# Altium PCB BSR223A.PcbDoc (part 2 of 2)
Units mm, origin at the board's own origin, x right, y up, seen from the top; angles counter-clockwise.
Board outline 76.2 x 76.2 mm, 4 copper layers (Top Layer, GND Layer 1, GND Layer 2, Bottom Layer), stack 1.554 mm thick; 57 components, 15 nets, 85 pads, 327 vias.
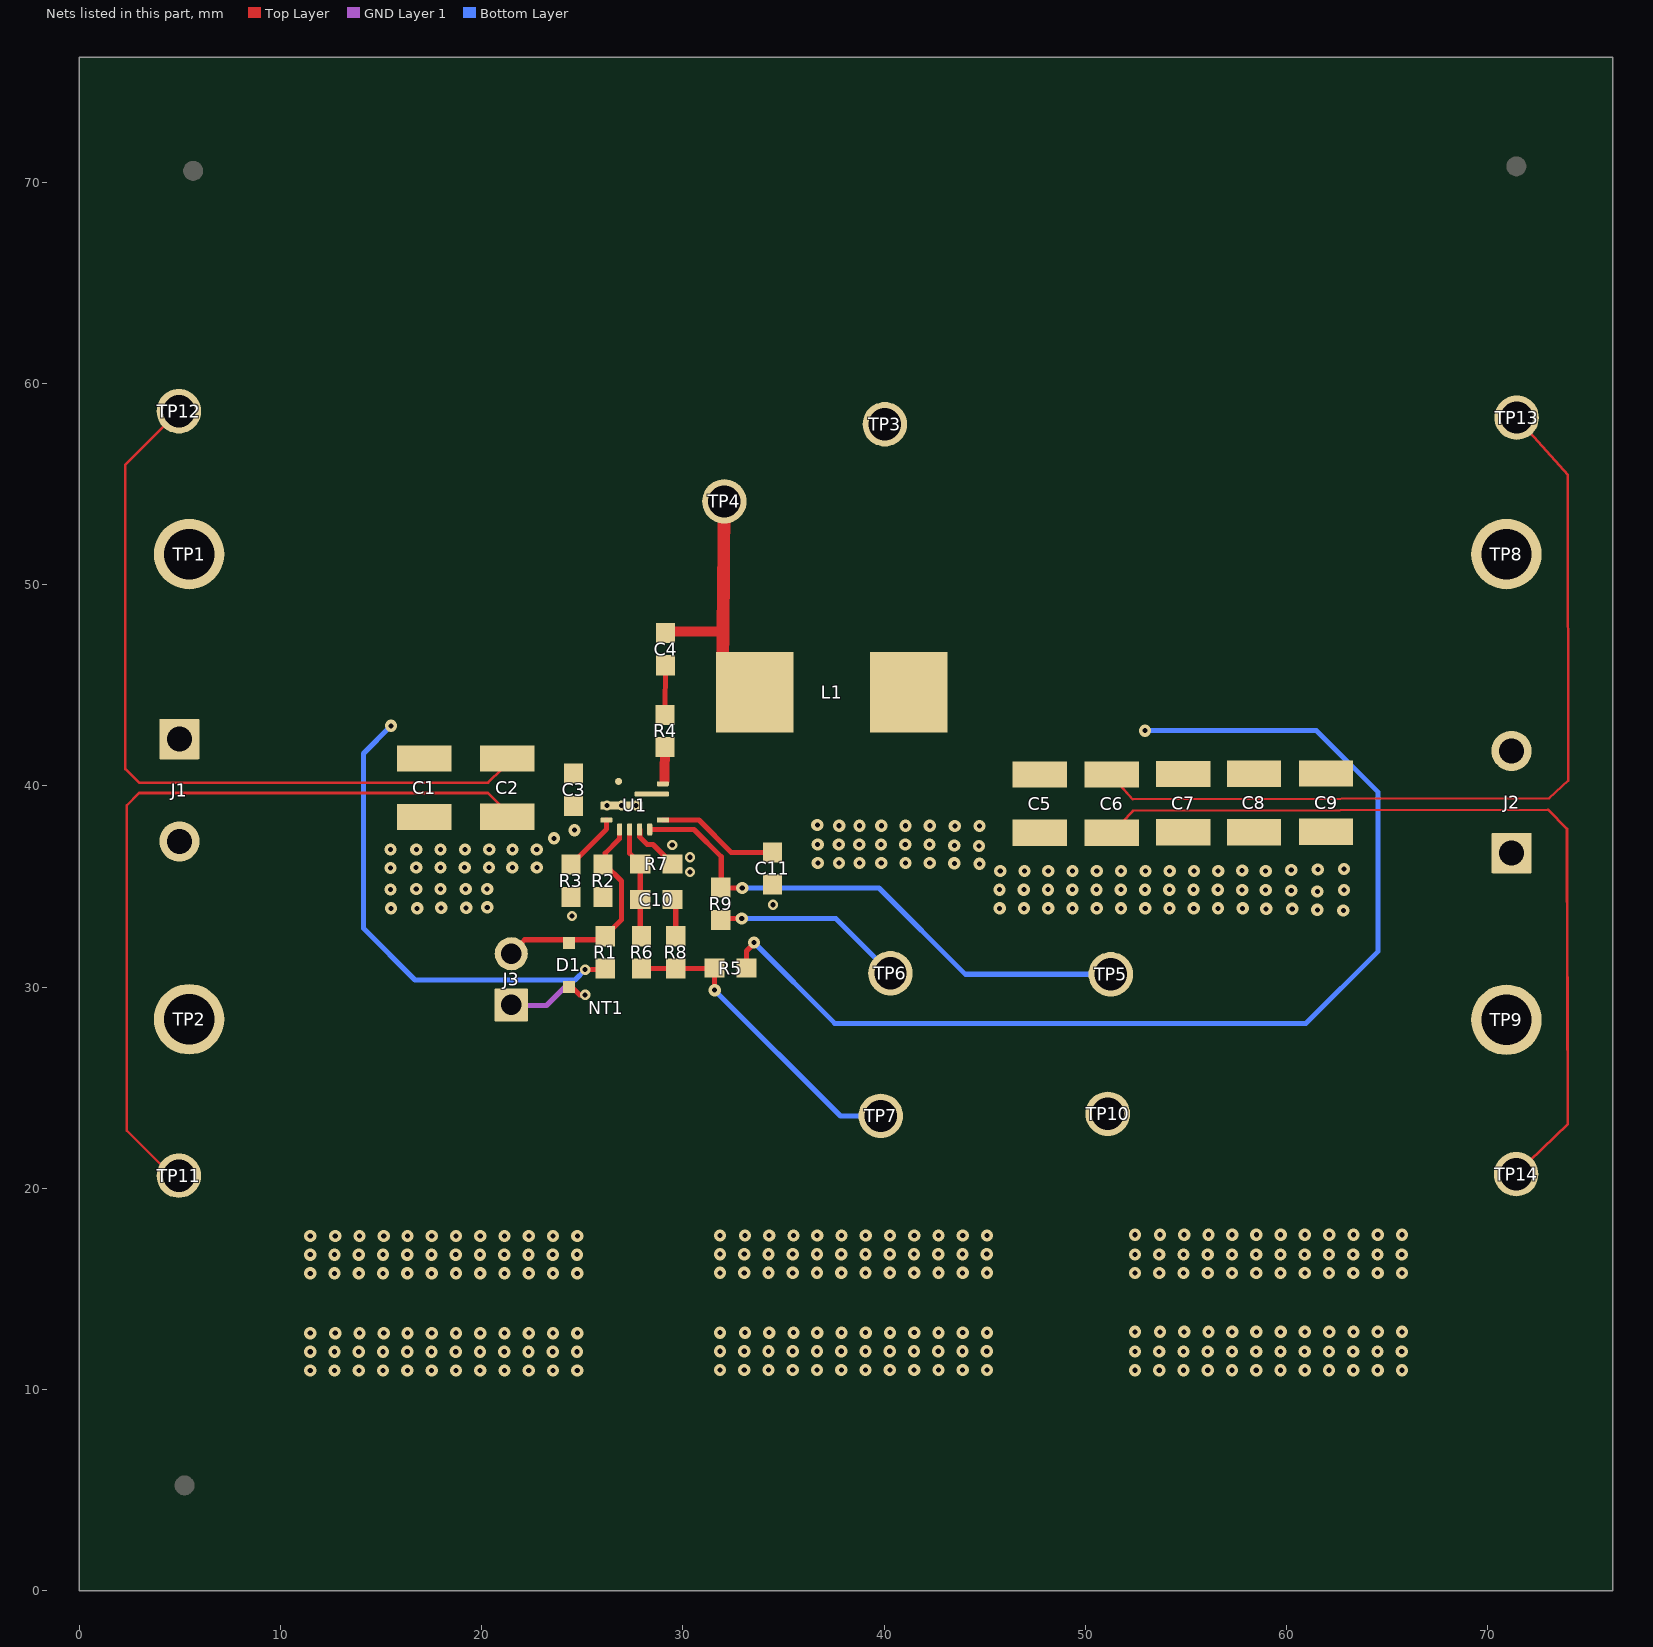
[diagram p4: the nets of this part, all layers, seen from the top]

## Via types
v1: diameter 0.61, hole 0.254, Top Layer to Bottom Layer, 317 vias
v2: diameter 0.508, hole 0.254, Top Layer to Bottom Layer, 10 vias

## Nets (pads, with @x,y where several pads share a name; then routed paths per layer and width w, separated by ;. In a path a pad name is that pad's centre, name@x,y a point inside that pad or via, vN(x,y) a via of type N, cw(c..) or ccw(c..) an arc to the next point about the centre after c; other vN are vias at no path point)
AGND: C11.2 D1.2 J3.1 NT1.1 R2.1 R3.1 R7.2 U1.3 | length 7.7
  Top Layer w0.254: J3.1@21.321,29.225 J3.1@21.463,29.083 ; D1.2@24.318,30.149 24.856,29.611 v2@25.105,29.611 ; U1.3@27.851,37.836 27.851,37.452 28.219,37.084 28.511,37.084 R7.2@29.477,36.119 R7.2@29.82,36.119
  GND Layer 1 w0.254: J3.1@21.463,29.083 23.216,29.083 24.333,30.201
  Bottom Layer w0.254: J3.1@21.463,29.083 J3.1@21.62,29.24
  other v2: 25.138,29.611 24.486,33.528 34.468,34.087 30.353,35.712 30.353,36.449 29.464,37.059
EN: D1.1 J3.2 R1.1 R2.2 U1.1 | length 11.5
  Top Layer w0.254: J3.2@21.364,31.524 21.463,31.623 J3.2@21.434,31.623 ; J3.2@21.463,31.674 22.139,32.349 25.961,32.349 R1.1@26.137,32.525 26.949,33.337 26.949,35.268 26.137,36.081 26.137,36.652 26.851,37.367 U1.1@26.851,37.836
FB: C10.2 R6.1 R7.1 U1.2 | length 5.5
  Top Layer w0.254: U1.2@27.351,37.836 27.351,36.644 R7.1@27.877,36.119 C10.2@27.877,34.341 R6.1@27.877,32.588
NetC1_2: C1.2 C2.2 C3.2 J1.1 R1.2 TP1.1 TP12.1 U1.8 | length 62
  Top Layer w0.127: TP12.1@4.952,58.61 2.297,55.956 2.297,40.832 2.972,40.157 20.32,40.157 C2.2@21.006,40.843
  Top Layer w0.254: v2(25.138,30.861) R1.2@26.073,30.861
  Bottom Layer w0.254: v1(15.494,42.977) 14.122,41.605 14.122,32.918 16.688,30.353 24.63,30.353 v2(25.138,30.861)
NetC4_2: C4.2 R4.2 | length 2.4
  Top Layer w0.254: R4.2@29.108,43.598 C4.2@29.134,46.033
NetC5_1: C5.1 C6.1 C7.1 C8.1 C9.1 J2.2 L1.2 R5.2 TP8.1 TP13.1 | length 98.3
  Top Layer w0.127: C6.1@51.694,40.061 52.342,39.327 73.045,39.39 73.99,40.259 73.965,55.448 TP13.1@71.426,58.293
  Top Layer w0.254: R5.2@33.16,30.937 33.16,31.793 33.528,32.162 v1(33.528,32.207)
  Bottom Layer w0.254: v1(33.528,32.207) 37.541,28.194 60.96,28.194 64.541,31.775 64.541,39.677 61.481,42.738 v1(52.959,42.738)
NetC10_1: C10.1 R8.1 | length 1.9
  Top Layer w0.254: C10.1@29.477,34.341 29.642,34.176 R8.1@29.642,32.525
NetC11_1: C11.1 U1.5 | length 6.1
  Top Layer w0.254: U1.5@28.998,38.299 30.789,38.299 32.398,36.69 C11.1@34.442,36.69
NetR3_2: R3.2 U1.10 | length 2.9
  Top Layer w0.254: R3.2@24.435,36.081 26.198,37.844 U1.10@26.198,38.299
NetR4_1: R4.1 U1.7 | length 1.9
  Top Layer w0.508: 29.083,40.252 R4.1@29.108,42.173
NetR5_1: R5.1 R6.2 R8.2 TP7.1 | length 15.5
  Top Layer w0.254: R6.2@27.94,30.925 R8.2@29.642,30.925 R5.1@31.547,30.925 ; R5.1@31.56,30.937 31.56,29.858 v1(31.572,29.845)
  Bottom Layer w0.254: v1(31.572,29.845) 37.821,23.597 TP7.1@39.827,23.597
NetR9_1: R9.1 TP5.1 U1.4 | length 26.8
  Top Layer w0.254: U1.4@28.348,37.829 30.548,37.829 31.902,36.474 31.902,34.963 31.94,34.925 v1(32.944,34.925)
  Bottom Layer w0.254: v1(32.944,34.925) 39.738,34.925 44.03,30.632 TP5.1@51.257,30.632
NetR9_2: R9.2 TP6.1 | length 9.6
  Top Layer w0.254: R9.2@31.877,33.338 31.94,33.401 v1(32.918,33.401)
  Bottom Layer w0.254: v1@32.944,33.376 v1(32.918,33.401) 37.592,33.401 TP6.1@40.31,30.683
PGND: C1.1 C2.1 C3.1 C5.2 C6.2 C7.2 C8.2 C9.2 J1.2 J2.1 NT1.2 TP2.1 TP3.1 TP9.1 TP10.1 TP11.1 TP14.1 U1.9 | length 80.9
  Top Layer w0.127: TP11.1@4.597,20.625 2.362,22.86 2.362,39.03 2.972,39.64 20.304,39.64 C2.1@20.98,38.964 ; C6.2@51.308,37.666 51.808,38.166 52.349,38.748 72.974,38.811 73.927,37.859 73.965,23.19 TP14.1@71.399,20.701
  Top Layer w0.254: TP11.1@4.597,20.625 TP11.1@4.952,20.625 ; C5.2@47.727,37.666 C5.2@47.955,37.895
  other v1: 11.481,10.947 12.687,10.947 13.893,10.947 15.099,10.947 16.305,10.947 17.511,10.947 18.717,10.947 19.923,10.947 21.129,10.947 22.335,10.947 23.541,10.947 24.747,10.947 31.837,10.973 33.043,10.973 34.249,10.973 35.455,10.973 36.661,10.973 37.867,10.973 39.073,10.973 40.279,10.973 41.485,10.973 42.691,10.973 43.897,10.973 45.103,10.973 52.457,10.96 53.663,10.96 54.869,10.96 56.075,10.96 57.281,10.96 58.487,10.96 59.693,10.96 60.899,10.96 62.105,10.96 63.311,10.96 64.517,10.96 65.723,10.96 11.481,11.874 12.686,11.874 13.891,11.874 15.096,11.874 16.301,11.874 17.506,11.874 18.711,11.874 19.916,11.874 21.121,11.874 22.326,11.874 23.531,11.874 24.736,11.874 31.837,11.9 33.042,11.9 34.247,11.9 35.452,11.9 36.657,11.9 37.862,11.9 39.067,11.9 40.272,11.9 41.477,11.9 42.682,11.9 43.887,11.9 45.092,11.9 52.457,11.887 53.662,11.887 54.867,11.887 56.072,11.887 57.277,11.887 58.482,11.887 59.687,11.887 60.892,11.887 62.097,11.887 63.302,11.887 64.507,11.887 65.712,11.887 11.481,12.802 12.722,12.802 13.926,12.802 15.131,12.802 16.31,12.802 17.515,12.802 18.72,12.802 19.924,12.802 21.136,12.802 22.341,12.802 23.546,12.802 24.75,12.802 31.837,12.827 33.078,12.827 34.283,12.827 35.487,12.827 36.667,12.827 37.871,12.827 39.076,12.827 40.281,12.827 41.493,12.827 42.697,12.827 43.902,12.827 45.107,12.827 52.457,12.865 53.698,12.865 54.902,12.865 56.107,12.865 57.286,12.865 58.491,12.865 59.696,12.865 60.9,12.865 62.112,12.865 63.317,12.865 64.522,12.865 65.726,12.865 11.481,15.773 12.687,15.773 13.893,15.773 15.099,15.773 16.305,15.773 17.511,15.773 18.717,15.773 19.923,15.773 21.129,15.773 22.335,15.773 23.541,15.773 24.747,15.773 31.837,15.799 33.043,15.799 34.249,15.799 35.455,15.799 36.661,15.799 37.867,15.799 39.073,15.799 40.279,15.799 41.485,15.799 42.691,15.799 43.897,15.799 45.103,15.799 52.457,15.786 53.663,15.786 54.869,15.786 56.075,15.786 57.281,15.786 58.487,15.786 59.693,15.786 60.899,15.786 62.105,15.786 63.311,15.786 64.517,15.786 65.723,15.786 11.481,16.7 12.686,16.7 13.891,16.7 15.096,16.7 16.301,16.7 17.506,16.7 18.711,16.7 19.916,16.7 21.121,16.7 22.326,16.7 23.531,16.7 24.736,16.7 31.837,16.726 33.042,16.726 34.247,16.726 35.452,16.726 36.657,16.726 37.862,16.726 39.067,16.726 40.272,16.726 41.477,16.726 42.682,16.726 43.887,16.726 45.092,16.726 52.457,16.713 53.662,16.713 54.867,16.713 56.072,16.713 57.277,16.713 58.482,16.713 59.687,16.713 60.892,16.713 62.097,16.713 63.302,16.713 64.507,16.713 65.712,16.713 11.481,17.628 12.722,17.628 13.926,17.628 15.131,17.628 16.31,17.628 17.515,17.628 18.72,17.628 19.924,17.628 21.136,17.628 22.341,17.628 23.546,17.628 24.75,17.628 31.837,17.653 33.078,17.653 34.283,17.653 35.487,17.653 36.667,17.653 37.871,17.653 39.076,17.653 40.281,17.653 41.493,17.653 42.697,17.653 43.902,17.653 45.107,17.653 52.457,17.691 53.698,17.691 54.902,17.691 56.107,17.691 57.286,17.691 58.491,17.691 59.696,17.691 60.9,17.691 62.112,17.691 63.317,17.691 64.522,17.691 65.726,17.691 62.814,33.807 61.519,33.833 58.979,33.884 60.274,33.884 15.494,33.909 16.789,33.909 45.734,33.909 46.94,33.909 48.146,33.909 49.352,33.909 50.558,33.909 51.764,33.909 52.97,33.909 54.176,33.909 55.382,33.909 56.588,33.909 57.81,33.909 17.983,33.934 19.228,33.934 20.275,33.96 61.519,34.747 60.223,34.798 57.785,34.823 58.953,34.823 62.84,34.823 15.469,34.849 45.732,34.836 46.937,34.836 48.142,34.836 49.347,34.836 50.552,34.836 51.757,34.836 52.962,34.836 54.167,34.836 55.372,34.836 56.577,34.836 16.747,34.874 17.953,34.874 19.202,34.874 20.269,34.874 45.767,35.763 46.972,35.763 48.151,35.763 49.356,35.763 50.561,35.763 51.765,35.763 52.977,35.763 54.182,35.763 55.387,35.763 56.591,35.763 58.953,35.763 57.785,35.789 60.223,35.814 61.544,35.839 62.84,35.865 15.469,35.916 16.741,35.941 17.946,35.941 19.151,35.941 20.356,35.941 21.52,35.941 22.739,35.941 44.729,36.119 43.485,36.144 36.701,36.157 37.754,36.157 38.768,36.157 39.85,36.157 41.056,36.157 42.262,36.157 15.469,36.83 16.749,36.83 17.954,36.83 19.166,36.83 20.371,36.83 21.527,36.83 22.733,36.83 44.704,37.008 43.485,37.033 36.692,37.084 37.744,37.084 38.76,37.084 39.841,37.084 41.046,37.084 42.251,37.084 23.597,37.389 24.613,37.795 37.759,38.011 38.776,38.011 39.857,38.011 41.061,38.011 42.266,38.011 43.51,37.998 44.729,37.998 36.678,38.049
  other v2: 26.224,39.019 26.948,39.019 27.672,39.019
SW: C4.1 L1.1 TP4.1 U1.6 | length 10.7
  Top Layer w0.508: C4.1@29.134,47.662 31.966,47.662
  Top Layer w0.635: L1.1@31.979,46.279 31.992,47.662 TP4.1@32.055,54.127
pads on no net: FID1.1 FID2.1 FID3.1 H9.0 H10.0 H11.0 H12.0 LBL1.0 SH-J3.0

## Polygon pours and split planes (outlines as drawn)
PGND on Top Layer "TOP_LAYER_PGND_P014" (solid, pour order 14): 21.742,39.599 21.234,39.091 3.048,39.091 2.718,38.76 2.718,22.987 4.597,21.107 4.597,21.083 4.191,20.574 2.032,22.732 2.032,39.23 2.68,39.878 0,39.878 0,0 76.2,0 76.225,38.887 73.466,38.878 74.308,38.036 74.292,23.035 72.06,20.803 71.536,21.297 73.603,23.364 73.603,37.522 72.796,38.329 50.817,38.329 50.208,38.862 36.652,38.862 35.865,38.075 35.865,30.077 34.826,28.997 24.252,28.997 23.597,29.652 23.597,35.724 26.155,38.406 28.092,38.481 28.194,38.633 28.194,39.141 27.737,39.599
NetC5_1 on Top Layer "TOP_LAYER_NETC5_1_P006" (solid, pour order 6): 50.183,39.117 50.869,39.929 72.949,39.929 73.609,40.538 73.609,55.347 71.463,57.772 71.552,57.861 71.971,58.28 74.371,55.601 74.397,40.056 73.508,39.13 76.2,39.167 76.2,76.2 37.109,76.2 37.109,50.673 38.176,49.606 38.176,39.753 38.786,39.117
NetC1_2 on Top Layer "TOP_LAYER_NETC1_2_P002" (solid, pour order 2): 21.819,39.878 21.184,40.716 2.973,40.692 2.642,41.023 2.642,55.829 4.826,58.014 4.394,58.445 4.394,58.511 1.998,56.115 1.974,56.115 1.974,56.055 1.974,40.495 2.591,39.878 0,39.878 0,76.2 36.805,76.2 36.805,50.775 35.839,49.657 29.134,49.657 28.346,48.87 28.346,40.056 28.169,39.878
AGND on Top Layer "TOP_LAYER_AGND_P044" (solid, pour order 44): 27.707,38.125 27.683,37.04 29.234,35.204 30.632,35.204 30.937,35.509 30.937,36.83 29.642,38.125
SW on Top Layer "TOP_LAYER_SW_P004" (solid, pour order 4): 28.143,39.802 29.108,39.802 29.87,40.564 29.87,48.514 30.658,49.301 35.077,49.301 36.093,48.285 36.093,39.802 35.049,38.757 28.55,38.786
AGND on Top Layer "TOP_LAYER_AGND_P069" (solid, remove dead copper, pour order 69): 34.874,33.757 34.925,33.757 35.158,33.985 35.158,35.53 34.86,35.828 34.062,35.828 33.752,35.518 33.752,33.99 33.985,33.757
AGND on Top Layer "TOP_LAYER_AGND_P042" (solid, remove dead copper, pour order 42): 24.874,33.248 25.269,33.757 26.397,33.757 26.726,34.087 26.726,35.001 26.391,35.204 23.956,35.204 23.859,35.052 23.859,33.419 24.029,33.248
PGND on GND Layer 1 "GND_LAYER_1_PGND_P073" (solid, remove dead copper, pour order 73): 11.43,76.225 0,76.2 0,0 76.2,0 76.2,76.2
AGND on GND Layer 1 "GND_LAYER_1_AGND_P070" (solid, remove dead copper, pour order 70): 24.994,29.235 23.597,30.632 23.597,35.724 25.908,38.035 25.984,38.125 28.448,38.125 28.753,38.43 35.564,38.43 35.865,38.075 35.865,30.785 34.315,29.235 24.994,29.235 23.597,30.632
PGND on GND Layer 2 "GND_LAYER_2_PGND_P074" (solid, remove dead copper, pour order 74): 0,76.2 0,68.555 0,0 76.2,0 76.2,76.2
PGND on Bottom Layer "BOTTOM_LAYER_PGND_P075" (solid, remove dead copper, pour order 75): 0,76.2 0,68.555 0,0 76.2,0 76.2,76.2

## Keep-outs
Keep-Out Layer:
  the board outline again, w0.254
  text ".Layer_Name" at 14.656,-21.806 h1.52

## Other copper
Top Layer:
  pour cut-out: 69.545,60.198 69.545,56.388 73.228,56.388 73.279,56.439 73.279,60.198
  pour cut-out: 69.571,22.581 69.571,18.796 69.545,18.771 73.228,18.771 73.254,18.796 73.254,22.555 73.279,22.581
  pour cut-out: 3.099,60.477 3.099,56.693 3.073,56.667 6.756,56.667 6.782,56.693 6.782,60.452 6.807,60.477
  pour cut-out: 3.15,22.504 3.15,18.72 3.124,18.694 6.807,18.694 6.833,18.72 6.833,22.479 6.858,22.504
  text ".Layer_Name" at 14.656,-21.806 h1.52
GND Layer 1:
  rectangle net PGND: 25.319,27.915 27.076,28.976
  rectangle net AGND: 25.319,29.224 27.026,29.972
  text ".Layer_Name" at 14.529,-21.641 h1.52
GND Layer 2:
  text ".Layer_Name" at 14.834,-21.844 h1.52
Bottom Layer:
  text ".Layer_Name" at 14.656,-21.806 h1.52

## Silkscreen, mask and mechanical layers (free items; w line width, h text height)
Top Overlay:
  text "L" at 18.796,28.491 h1.02
  text "'.PRJ_Number'.PCB_Rev" at 32.977,3.957 h2.75
  text ".Layer_Name" at 14.656,-21.806 h1.52
Bottom Overlay:
  text ".Layer_Name" at 14.656,-21.806 h1.52
Top Paste:
  text ".Layer_Name" at 14.656,-21.806 h1.52
Bottom Paste:
  text ".Layer_Name" at 14.656,-21.806 h1.52
Top Solder:
  rectangle: 38.633,41.859 45.491,47.447
  rectangle: 31.039,41.834 35.636,47.473
  text ".Layer_Name" at 14.656,-21.806 h1.52
  text ".Layer_Name" at 14.656,-21.806 h1.52
Bottom Solder:
  text ".Layer_Name" at 14.656,-21.806 h1.52
Drill Guide:
  text ".Layer_Name" at 14.656,-21.806 h1.52
M1 Board Outline:
  the board outline again, w0.254
  text ".Layer_Name" at 14.656,-21.806 h1.52
M2 Board Dimensions:
  rectangle: 3.175,-10.16 12.7,-6.985
  rectangle: 0,-6.985 3.175,-3.81
  lines w0.178: 0,-6.985 25.4,-6.985 ; 3.175,-10.16 3.175,-3.81 ; 6.35,-10.16 6.35,-3.81 ; 12.7,-10.16 12.7,-3.81 ; 19.05,-10.16 19.05,-3.81 ; 0,-10.16 0,-3.81 25.4,-3.81 25.4,-10.16 0,-10.16
  text ".Layer_Name" at 14.656,-21.806 h1.52
M3 3D STEP Top:
  text ".Layer_Name" at 14.656,-21.806 h1.52
M4 3D STEP Bottom:
  text ".Layer_Name" at 14.656,-21.806 h1.52
M5 Assembly Top:
  lines w0.254: -7.417,-23.626 160.223,-23.626 ; -7.417,-18.462 160.274,-18.462 ; -7.417,-13.297 -7.417,-28.791 94.31,-28.791 160.274,-28.791 160.274,-13.297 -7.404,-13.297 -7.404,-28.791 32.614,-28.791 ; 55.194,-28.791 55.194,-13.297 ; 87.376,-18.462 87.376,-13.297 ; 108.712,-18.462 108.712,-13.297 ; 124.511,-28.956 124.511,-23.804
  text "COMPONENTS MARKED 'DNP' SHOULD NOT BE POPULATED." at 29.299,-8.09 h1.52
  text "ASSEMBLY VARIANT:" at 29.286,-11.024 h1.52
  text ".VariantName" at 55.601,-11.024 h1.52
  text "PCB VIEWED FROM TOP SIDE" at -5.804,-16.654 h1.52
  text "BOARD #:" at 57.099,-16.654 h1.52
  text ".PRJ_Number" at 70.955,-16.654 h1.52
  text "REV:" at 92.405,-16.654 h1.52
  text ".PCB_Rev" at 99.809,-16.654 h1.52
  text "SVN REV:" at 113.69,-16.654 h1.52
  text ".VersionControl_RevNumber" at 126.543,-16.654 h1.52
  text "TID #:" at 57.099,-21.819 h1.52
  text ".TID" at 70.955,-21.819 h1.52
  text "PLOT NAME =" at -5.804,-27.034 h1.52
  text ".plot_File_Name" at 14.656,-27.034 h1.52
  text "GENERATED    :" at 57.15,-27.034 h1.52
  text ".Print_Date" at 79.235,-27.034 h1.52
  text ".Print_Time" at 97.752,-27.034 h1.52
  text "TEXAS INSTRUMENTS" at 129.87,-27.034 h1.52
M6 Assembly Bottom:
  lines w0.254: -7.429,-18.474 160.261,-18.474 ; -7.379,-23.639 160.261,-23.639 ; 28.334,-28.969 28.334,-23.817 ; 44.133,-18.474 44.133,-13.31 ; 65.468,-18.474 65.468,-13.31 ; 97.65,-28.804 97.65,-13.31 ; 120.231,-28.804 160.249,-28.804 160.249,-13.31 -7.429,-13.31 -7.429,-28.804 58.534,-28.804 160.261,-28.804 160.261,-13.31
  text "COMPONENTS MARKED 'DNP' SHOULD NOT BE POPULATED." at 154.991,-8.077 h1.52
  text ".VariantName" at 128.473,-11.024 h1.52
  text "ASSEMBLY VARIANT:" at 154.864,-11.024 h1.52
  text ".VersionControl_RevNumber" at 26.302,-16.667 h1.52
  text "SVN REV:" at 39.154,-16.667 h1.52
  text ".PCB_Rev" at 53.035,-16.667 h1.52
  text "REV:" at 60.439,-16.667 h1.52
  text ".PRJ_Number" at 81.89,-16.667 h1.52
  text "BOARD #:" at 95.745,-16.667 h1.52
  text "PCB VIEWED FROM BOTTOM SIDE" at 158.648,-16.667 h1.52
  text ".TID" at 81.89,-21.831 h1.52
  text "TID #:" at 95.745,-21.831 h1.52
  text "TEXAS INSTRUMENTS" at 22.974,-27.047 h1.52
  text ".Print_Time" at 55.093,-27.047 h1.52
  text ".Print_Date" at 73.609,-27.047 h1.52
  text "GENERATED    :" at 95.694,-27.047 h1.52
  text ".plot_File_Name" at 138.189,-27.047 h1.52
  text "PLOT NAME =" at 158.648,-27.047 h1.52
M9 Title Sheet:
  drawing of 57 lines, arcs and shapes, not listed
  text "1" at 18.792,204.127 h1.78
  text "2" at 82.182,204.127 h1.78
  text "3" at 145.411,204.127 h1.78
  text "4" at 209.08,204.127 h1.78
  text "5" at 272.555,204.127 h1.78
  text "6" at 336.182,204.127 h1.78
  text "A" at -10.579,175.095 h1.78
  text "A" at 365.341,175.095 h1.78
  text "B" at -10.579,114.643 h1.78
  text "B" at 365.341,114.643 h1.78
  text "C" at -10.579,54.318 h1.78
  text "C" at 365.341,54.318 h1.78
  text "PROJECT TITLE:" at 288.125,7.048 h1.14
  text ".PRJ_Title" at 289.395,3.662 h1.78
  text "DESIGNED FOR:" at 288.125,-0.597 h1.14
  text ".PRJ_Customer" at 289.395,-4.153 h1.78
  text "D" at -10.579,-5.88 h1.78
  text "D" at 365.341,-5.88 h1.78
  text "FILE NAME:" at 288.125,-8.217 h1.14
  text ".PCB_File_Name_No_Path" at 289.395,-11.265 h1.78
  text "Texas Instruments (TI) and/or its licensors do not warrant the accuracy or completeness of this specification" at 161.9,-15.376 h1.14
  text "ENGINEER:" at 288.125,-15.583 h1.14
  text "LAYOUT BY:" at 326.352,-15.583 h1.14
  text "or any information contained therein. TI and/or its licensors do not warrant that this design will meet" at 160.757,-18.237 h1.14
  text ".PRJ_Engineer" at 289.395,-19.52 h1.78
  text ".PCB_Layout" at 327.635,-19.52 h1.78
  text "the specifications, will be suitable for your application or fit for any particular purpose, or will operate in" at 160.757,-21.099 h1.14
  text ".Layer_Name" at 14.656,-21.806 h1.52
  text "ALTIUM DESIGNER VERSION:" at 326.352,-23.457 h1.14
  text "an implementation. TI and/or its licensors do not warrant that the design is production worthy. You should" at 160.757,-23.961 h1.14
  text "completely validate and test your design implementation to confirm the system functionality for your application." at 161.9,-26.822 h1.14
  text ".print_Scale" at 289.395,-26.843 h1.78
  text ".Application_BuildNumber" at 327.635,-26.843 h1.78
  text "1" at 18.792,-32.093 h1.78
  text "2" at 82.182,-32.093 h1.78
  text "3" at 145.411,-32.093 h1.78
  text "4" at 209.08,-32.093 h1.78
  text "5" at 272.555,-32.093 h1.78
  text "6" at 336.182,-32.093 h1.78
M10 Fab Notes:
  drawing of 189 lines, arcs and shapes, not listed
  text "DESIGN INFORMATION" at 314.503,161.447 h1.52
  text "MIN. TRACK WIDTH:" at 298.131,158.091 h1.52
  text "8" at 325.976,158.091 h1.52
  text "MIL" at 329.907,158.091 h1.52
  text "MIN. CLEARANCE:" at 298.131,154.938 h1.52
  text "0.2" at 324.452,154.938 h1.52
  text "mm" at 329.907,154.938 h1.52
  text "MIN. VIA PAD SIZE:" at 298.131,151.785 h1.52
  text "24" at 325.214,151.785 h1.52
  text "MIL" at 329.907,151.785 h1.52
  text "0.05mm (2MIL)" at 315.784,148.486 h1.52
  text "MINIMUM ANNULAR RING" at 289.769,148.277 h1.52
  text "EXTERNAL" at 333.768,148.277 h1.52
  text "PER" at 294.849,145.48 h1.52
  text "IPC-D-275 CLASS 2 LEVEL C" at 300.437,145.48 h1.52
  text "MIL, HOLES" at 338.238,142.928 h1.52
  text "+/-" at 328.27,142.709 h1.52
  text "+/-" at 349.961,142.709 h1.52
  text "REGISTRATION TOLERANCES:" at 289.769,142.682 h1.52
  text "METAL" at 320.243,142.682 h1.52
  text "5" at 334.879,142.683 h1.52
  text "3" at 356.037,142.683 h1.52
  text "MIL" at 358.99,142.682 h1.52
  text "HOLE SIZE TOLERANCE (UNLESS OTHERWISE SPECIFIED):" at 289.769,140.185 h1.52
  text "+/-" at 349.961,140.112 h1.52
  text "3" at 356.037,140.085 h1.52
  text "MIL" at 358.99,140.085 h1.52
  text "MATERIAL:" at 287.87,136.589 h1.52
  text "FR-4 High Tg" at 312.926,133.324 h1.52
  text "X" at 309.257,133.122 h1.52
  text "FR-408" at 298.563,133.007 h1.52
  text "OTHER" at 336.358,133.007 h1.52
  text "62 MIL (1.6mm) +/-10%" at 306.694,129.374 h1.52
  text "X" at 303.643,129.312 h1.52
  text "THICKNESS:" at 289.769,129.165 h1.52
  text "OTHER" at 339.33,129.165 h1.52
  text "TOLERANCE:" at 289.769,125.652 h1.52
  text "X" at 311.314,125.652 h1.52
  text "ANSI IPC-6012 TYPE 3 CLASS 2" at 315.836,125.652 h1.52
  text "OTHER +/-" at 315.835,121.989 h1.52
  text "BOW & TWIST:" at 289.769,118.302 h1.52
  text "X" at 311.314,118.302 h1.52
  text "ANSI IPC-6012 TYPE 3 CLASS 2" at 315.836,118.302 h1.52
  text "OTHER +/-" at 315.835,114.576 h1.52
  text "DRILLING:" at 287.87,111.258 h1.52
  text "NC_DRILL FILES" at 332.599,108.586 h1.52
  text "REFERENCE:" at 289.769,108.486 h1.52
  text "X" at 306.463,108.484 h1.52
  text "AS SHOWN" at 310.984,108.486 h1.52
  text "X" at 329.348,108.486 h1.52
  text "OTHER" at 340.168,104.873 h1.52
  text "PTH COPPER THICKNESS:" at 289.761,104.783 h1.52
  text "X" at 318.697,104.783 h1.52
  text "20-30 um" at 321.948,104.783 h1.52
  text "BOARD FINISH:" at 287.87,101.034 h1.52
  text "SILKSCREEN:" at 291.812,98.237 h1.52
  text "X" at 316.14,98.237 h1.52
  text "TOP" at 319.112,98.237 h1.52
  text "X" at 329.094,98.237 h1.52
  text "BOTTOM" at 332.091,98.237 h1.52
  text "SILKSCREEN COLOR:" at 291.812,94.295 h1.52
  text "X" at 316.115,94.295 h1.52
  text "WHITE" at 319.112,94.295 h1.52
  text "OTHER" at 332.091,94.295 h1.52
  text "X" at 319.442,90.652 h1.52
  text "GREEN" at 322.439,90.652 h1.52
  text "OTHER" at 338.136,90.652 h1.52
  text "SOLDER RESIST COLOR:" at 291.812,90.477 h1.52
  text "X" at 319.442,86.734 h1.52
  text "MATTE" at 322.439,86.734 h1.52
  text "SEMI-GLOSS" at 338.125,86.717 h1.52
  text "IMMERSION GOLD (ENIG)" at 314.819,82.345 h1.52
  text "ENEPIG" at 348.793,82.162 h1.52
  text "SURFACE FINISH:" at 287.87,82.136 h1.52
  text "X" at 310.298,82.136 h1.52
  text "IMM. TIN/SILVER OR EQUIV" at 296.24,78.649 h1.52
  text "OTHER" at 332.599,78.549 h1.52
  text "ARRAY/PANEL:" at 287.87,74.602 h1.52
  text "CUT AND TRIM PER M1 BOARD OUTLINE" at 314.819,74.393 h1.52
  text "N.C. ROUTE" at 314.819,70.94 h1.52
  text "X" at 332.295,70.94 h1.52
  text "V. SCORE" at 336.816,70.94 h1.52
  text "CERTIFICATION:" at 287.87,67.66 h1.52
  text "MATERIALS AND WORKMANSHIP FOR ALL PCBS" at 306.285,67.66 h1.52
  text "TO MEET OR EXCEED THE REQUIREMENTS OF:" at 306.285,65.271 h1.52
  text "X" at 297.078,62.003 h1.52
  text "ANSI IPC-A-600F CLASS ->" at 300.329,62.003 h1.52
  text "X" at 342.188,62.003 h1.52
  text "2" at 344.982,62.003 h1.52
  text "1" at 336.981,61.965 h1.52
  text "3" at 353.973,61.965 h1.52
  text "X" at 317.702,58.252 h1.52
  text "RoHS" at 320.953,58.252 h1.52
  text "OTHER" at 337.321,58.252 h1.52
  text "PER ORDER" at 347.407,58.252 h1.52
  text "ALL BOARDS MUST MEET OR EXCEED UL94-V0 REQUIREMENTS." at 288.569,54.345 h1.52
  text "PCB MUST BEAR THE UL94V-0 UL REGISTERED MATERIAL ID NUMBER" at 288.569,51.397 h1.52
  text "ADDITIONAL REQUIREMENTS:" at 287.87,47.094 h1.52
  text "MICROSECTION:" at 289.769,44.373 h1.52
  text "YES" at 312.775,44.373 h1.52
  text "REQUIRED" at 334.657,40.707 h1.52
  text "BARE BOARD ELEC. TEST:" at 289.769,40.634 h1.52
  text "NONE" at 322.935,40.634 h1.52
  text "X" at 331.66,40.634 h1.52
  text "PER ORDER" at 349.693,40.634 h1.52
  text "XX MIL VIAS REQUIRE NON-CONDUCTIVE FILL AND PLANARIZE" at 294.04,35.428 h1.5
  text "XX MIL VIAS REQUIRE CONDUCTIVE FILL AND PLANARIZE" at 294.243,32.787 h1.52
  text "OUTER XX MIL TRACES REQUIRE 50 OHM SINGLE-ENDED IMPEDANCE" at 294.218,28.637 h1.47
  text "LAYER 2 & 3 (INNER LAYERS) XX MIL WIDE, XX MIL SPACE / TRACES REQUIRE 100 OHM DIFFERENTIAL IMPEDANCE" at 294.015,22.65 h1.52
  text ".Layer_Name" at 14.656,-21.806 h1.52
M11 Gerber Information:
  lines w0.254: -7.417,-23.626 160.223,-23.626 ; -7.417,-18.462 160.274,-18.462 ; -7.417,-13.297 -7.417,-28.791 94.31,-28.791 160.274,-28.791 160.274,-13.297 -7.404,-13.297 -7.404,-28.791 32.614,-28.791 ; 55.194,-28.791 55.194,-13.297 ; 87.376,-18.462 87.376,-13.297 ; 108.712,-18.462 108.712,-13.297 ; 124.511,-28.956 124.511,-23.804
  text "ALL ARTWORK VIEWED FROM TOP SIDE" at -5.804,-16.654 h1.52
  text "BOARD #:" at 57.099,-16.654 h1.52
  text ".PRJ_Number" at 70.955,-16.654 h1.52
  text "REV:" at 92.405,-16.654 h1.52
  text ".PCB_Rev" at 99.809,-16.654 h1.52
  text "SVN REV:" at 113.69,-16.654 h1.52
  text ".VersionControl_RevNumber" at 126.543,-16.654 h1.52
  text "LAYER NAME =" at -5.804,-21.806 h1.52
  text "TID #:" at 57.099,-21.819 h1.52
  text ".TID" at 70.955,-21.819 h1.52
  text "PLOT NAME =" at -5.804,-27.034 h1.52
  text ".plot_File_Name" at 14.656,-27.034 h1.52
  text "GENERATED    :" at 57.15,-27.034 h1.52
  text ".Print_Date" at 79.235,-27.034 h1.52
  text ".Print_Time" at 97.752,-27.034 h1.52
  text "TEXAS INSTRUMENTS" at 129.87,-27.034 h1.52
M12 Stackup:
  drawing of 269 lines, arcs and shapes, not listed
  text "Layer" at 84.991,57.302 h1.52
  text "Name" at 95.402,57.302 h1.52
  text "Material" at 117.24,57.302 h1.52
  text "Thickness" at 139.079,57.302 h1.52
  text "Constant" at 155.584,57.302 h1.52
  text "Board Layer Stack" at 170.059,57.302 h1.52
  text "Top Overlay" at 95.402,54.254 h1.52
  text "Top Solder" at 95.402,51.206 h1.52
  text "Solder Resist" at 117.24,51.206 h1.52
  text "0.40mil" at 139.079,51.206 h1.52
  text "3.5" at 155.584,51.206 h1.52
  text "1" at 84.991,48.158 h1.52
  text "Top Layer" at 95.402,48.158 h1.52
  text "2.84mil" at 139.079,48.158 h1.52
  text "Dielectric1" at 95.402,45.11 h1.52
  text "FR-4" at 117.24,45.11 h1.52
  text "6.00mil" at 139.079,45.11 h1.52
  text "4.8" at 155.584,45.11 h1.52
  text "2" at 84.991,42.062 h1.52
  text "GND Layer 1" at 95.402,42.062 h1.52
  text "1.42mil" at 139.079,42.062 h1.52
  text "Dielectric 3" at 95.402,39.014 h1.52
  text "40.70mil" at 139.079,39.014 h1.52
  text "4.8" at 155.584,39.014 h1.52
  text "3" at 84.991,35.966 h1.52
  text "GND Layer 2" at 95.402,35.966 h1.52
  text "1.42mil" at 139.079,35.966 h1.52
  text "Dielectric 2" at 95.402,32.918 h1.52
  text "6.00mil" at 139.079,32.918 h1.52
  text "4.8" at 155.584,32.918 h1.52
  text "4" at 84.991,29.87 h1.52
  text "Bottom Layer" at 95.402,29.87 h1.52
  text "2.84mil" at 139.079,29.87 h1.52
  text "Bottom Solder" at 95.402,26.822 h1.52
  text "Solder Resist" at 117.24,26.822 h1.52
  text "0.40mil" at 139.079,26.822 h1.52
  text "3.5" at 155.584,26.822 h1.52
  text ".Layer_Name" at 14.656,-21.806 h1.52
M13 Component Bodies Top:
  text ".Layer_Name" at 14.656,-21.806 h1.52
M14 Component Bodies Bottom:
  text ".Layer_Name" at 14.656,-21.806 h1.52
M15 Courtyards Top:
  text ".Layer_Name" at 14.656,-21.806 h1.52
M16 Courtyards Bottom:
  text ".Layer_Name" at 14.656,-21.806 h1.52
Drill Drawing:
  circle w0.254: c85.306,66.894 r0.702
  lines w0.254: 84.604,69.35 85.306,69.701 86.007,69.35 85.657,70.052 86.007,70.754 85.306,70.403 84.604,70.754 84.955,70.052 84.604,69.35 ; 84.604,73.911 86.007,73.911 85.306,72.508 84.604,73.911 ; 84.604,75.666 86.007,75.666 86.007,77.069 84.604,77.069 84.604,75.666 ; 84.604,79.174 84.955,79.174 85.306,78.823 85.657,79.174 86.007,79.174 85.657,79.525 86.007,79.876 85.657,79.876 85.306,80.227 84.955,79.876 84.604,79.876 84.955,79.525 84.604,79.174
  lines w0.305: 83.332,65.245 165.411,65.245 ; 83.332,81.034 165.411,81.034 ; 91.913,62.087 91.913,84.192 ; 100.346,62.087 100.346,84.192 ; 116.515,62.087 116.515,84.192 ; 123.097,62.087 123.097,84.192 ; 132.626,62.087 132.626,84.192 ; 151.024,62.087 151.024,84.192 ; 83.332,62.087 165.411,62.087 165.411,84.192 83.332,84.192 83.332,62.087
  text "Symbol" at 85.226,81.981 h1.83
  text "Quantity" at 92.861,81.981 h1.83
  text "Finished Hole Size" at 101.294,81.981 h1.83
  text "Plated" at 117.462,81.981 h1.83
  text "Hole Type" at 124.044,81.981 h1.83
  text "Drill Layer Pair" at 133.573,81.981 h1.83
  text "Hole Tolerance" at 151.971,81.981 h1.83
  text "327" at 92.861,78.823 h1.52
  text "10.00mil (0.254mm)" at 101.294,78.823 h1.52
  text "PTH" at 117.462,78.823 h1.52
  text "Round" at 124.044,78.823 h1.52
  text "Top Layer - Bottom Layer" at 133.573,78.823 h1.52
  text "2" at 92.861,75.666 h1.52
  text "40.00mil (1.016mm)" at 101.294,75.666 h1.52
  text "PTH" at 117.462,75.666 h1.52
  text "Round" at 124.044,75.666 h1.52
  text "Top Layer - Bottom Layer" at 133.573,75.666 h1.52
  text "4" at 92.861,72.508 h1.52
  text "49.21mil (1.250mm)" at 101.294,72.508 h1.52
  text "PTH" at 117.462,72.508 h1.52
  text "Round" at 124.044,72.508 h1.52
  text "Top Layer - Bottom Layer" at 133.573,72.508 h1.52
  text "10" at 92.861,69.35 h1.52
  text "63.00mil (1.600mm)" at 101.294,69.35 h1.52
  text "PTH" at 117.462,69.35 h1.52
  text "Round" at 124.044,69.35 h1.52
  text "Top Layer - Bottom Layer" at 133.573,69.35 h1.52
  text "4" at 92.861,66.192 h1.52
  text "98.43mil (2.500mm)" at 101.294,66.192 h1.52
  text "PTH" at 117.462,66.192 h1.52
  text "Round" at 124.044,66.192 h1.52
  text "Top Layer - Bottom Layer" at 133.573,66.192 h1.52
  text "347 Total" at 92.861,63.035 h1.52
  text ".Layer_Name" at 14.656,-21.806 h1.52
M17 Embedded Cavity:
  text ".Layer_Name" at 14.656,-21.806 h1.52
M18 Embedded Assembly:
  text ".Layer_Name" at 14.656,-21.806 h1.52
M19 Embedded Keepout:
  text ".Layer_Name" at 14.656,-21.806 h1.52

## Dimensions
0,0 to 76.2,0 on M2 Board Dimensions
0,0 to 0,76.2 on M2 Board Dimensions
0,-10.16 to 25.4,-10.16 on M2 Board Dimensions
